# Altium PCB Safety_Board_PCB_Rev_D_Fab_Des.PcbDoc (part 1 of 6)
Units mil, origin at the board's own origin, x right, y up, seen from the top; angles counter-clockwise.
Board outline 11000 x 4400 mil, 6 copper layers (L1-TOP, L2-Plane, L3-Signal, L4-Signal, L5-Plane, L6-BOT); 712 components, 540 nets, 2214 pads, 875 vias.
Unrouted connection lines stored in the file: 3.
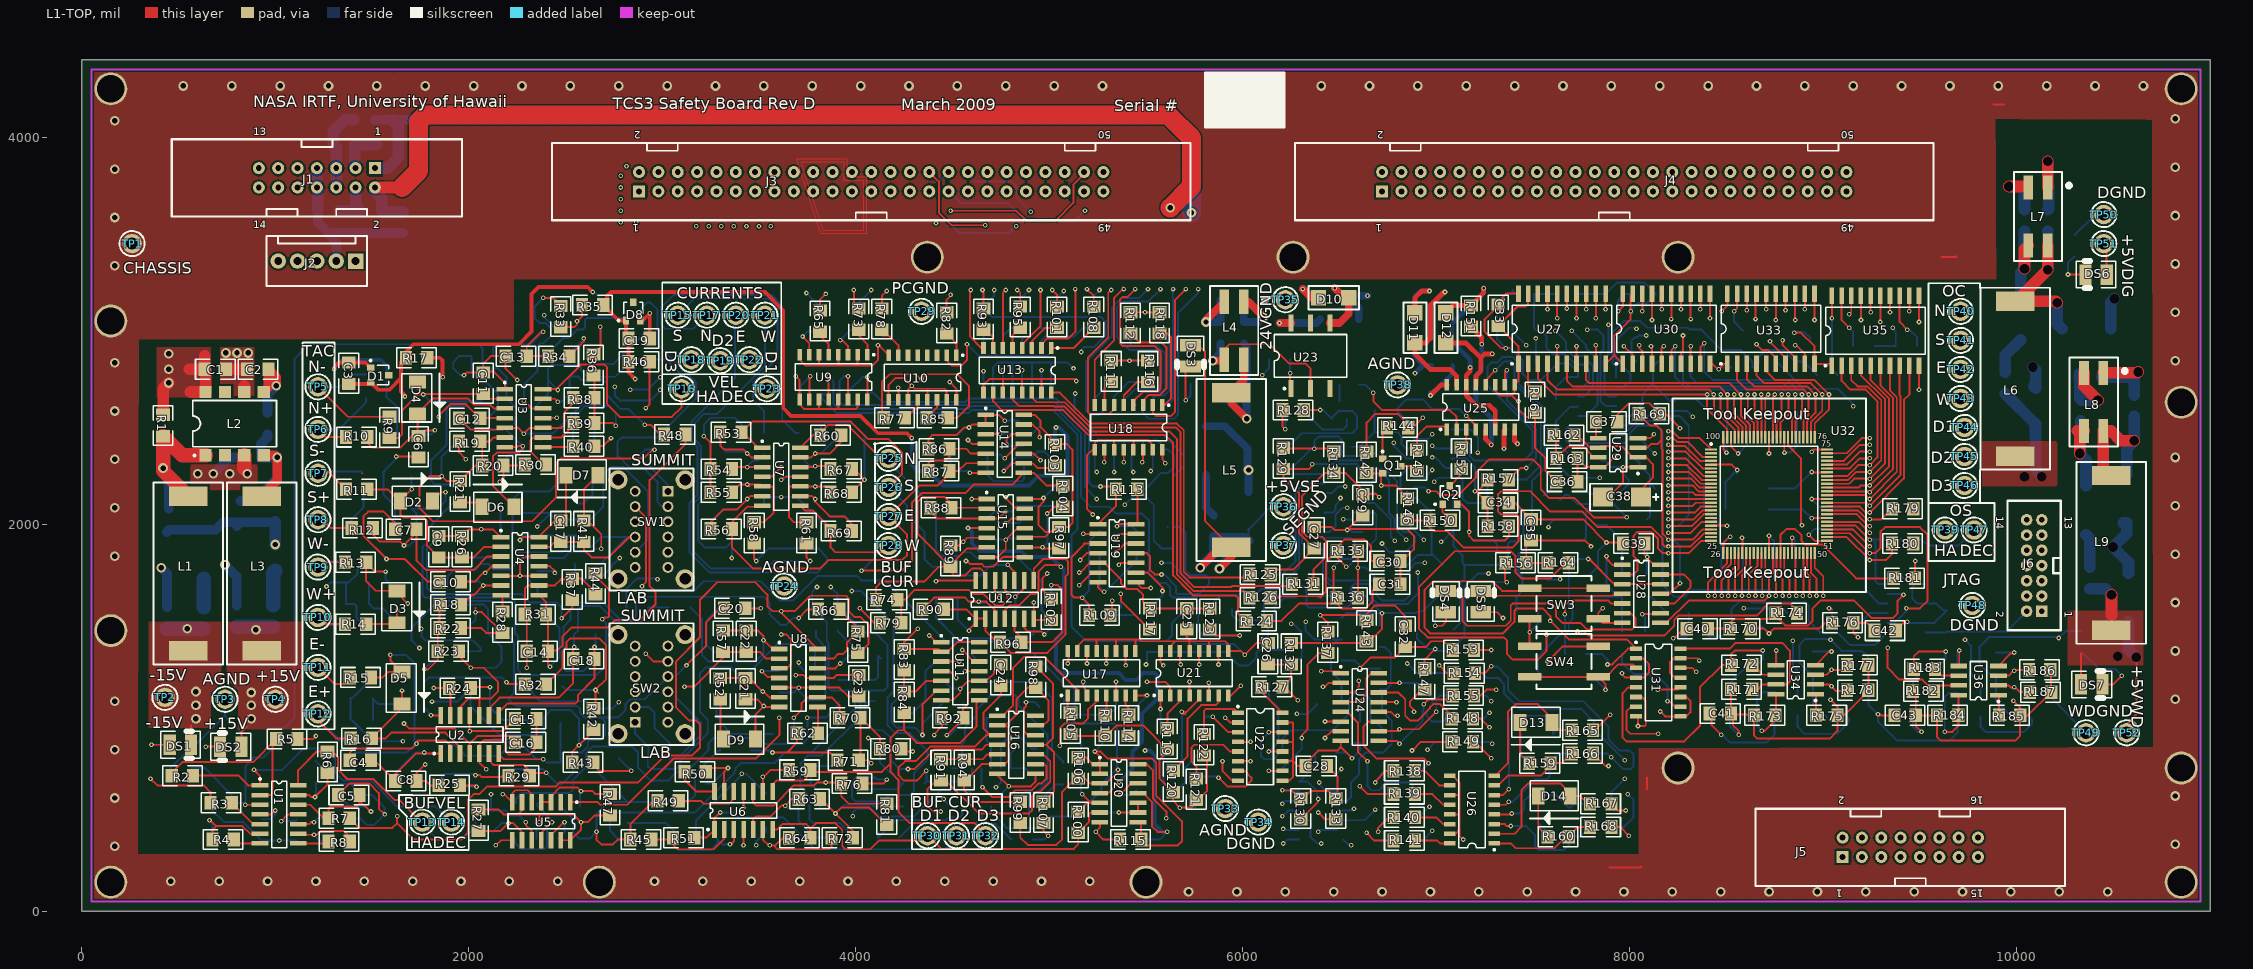
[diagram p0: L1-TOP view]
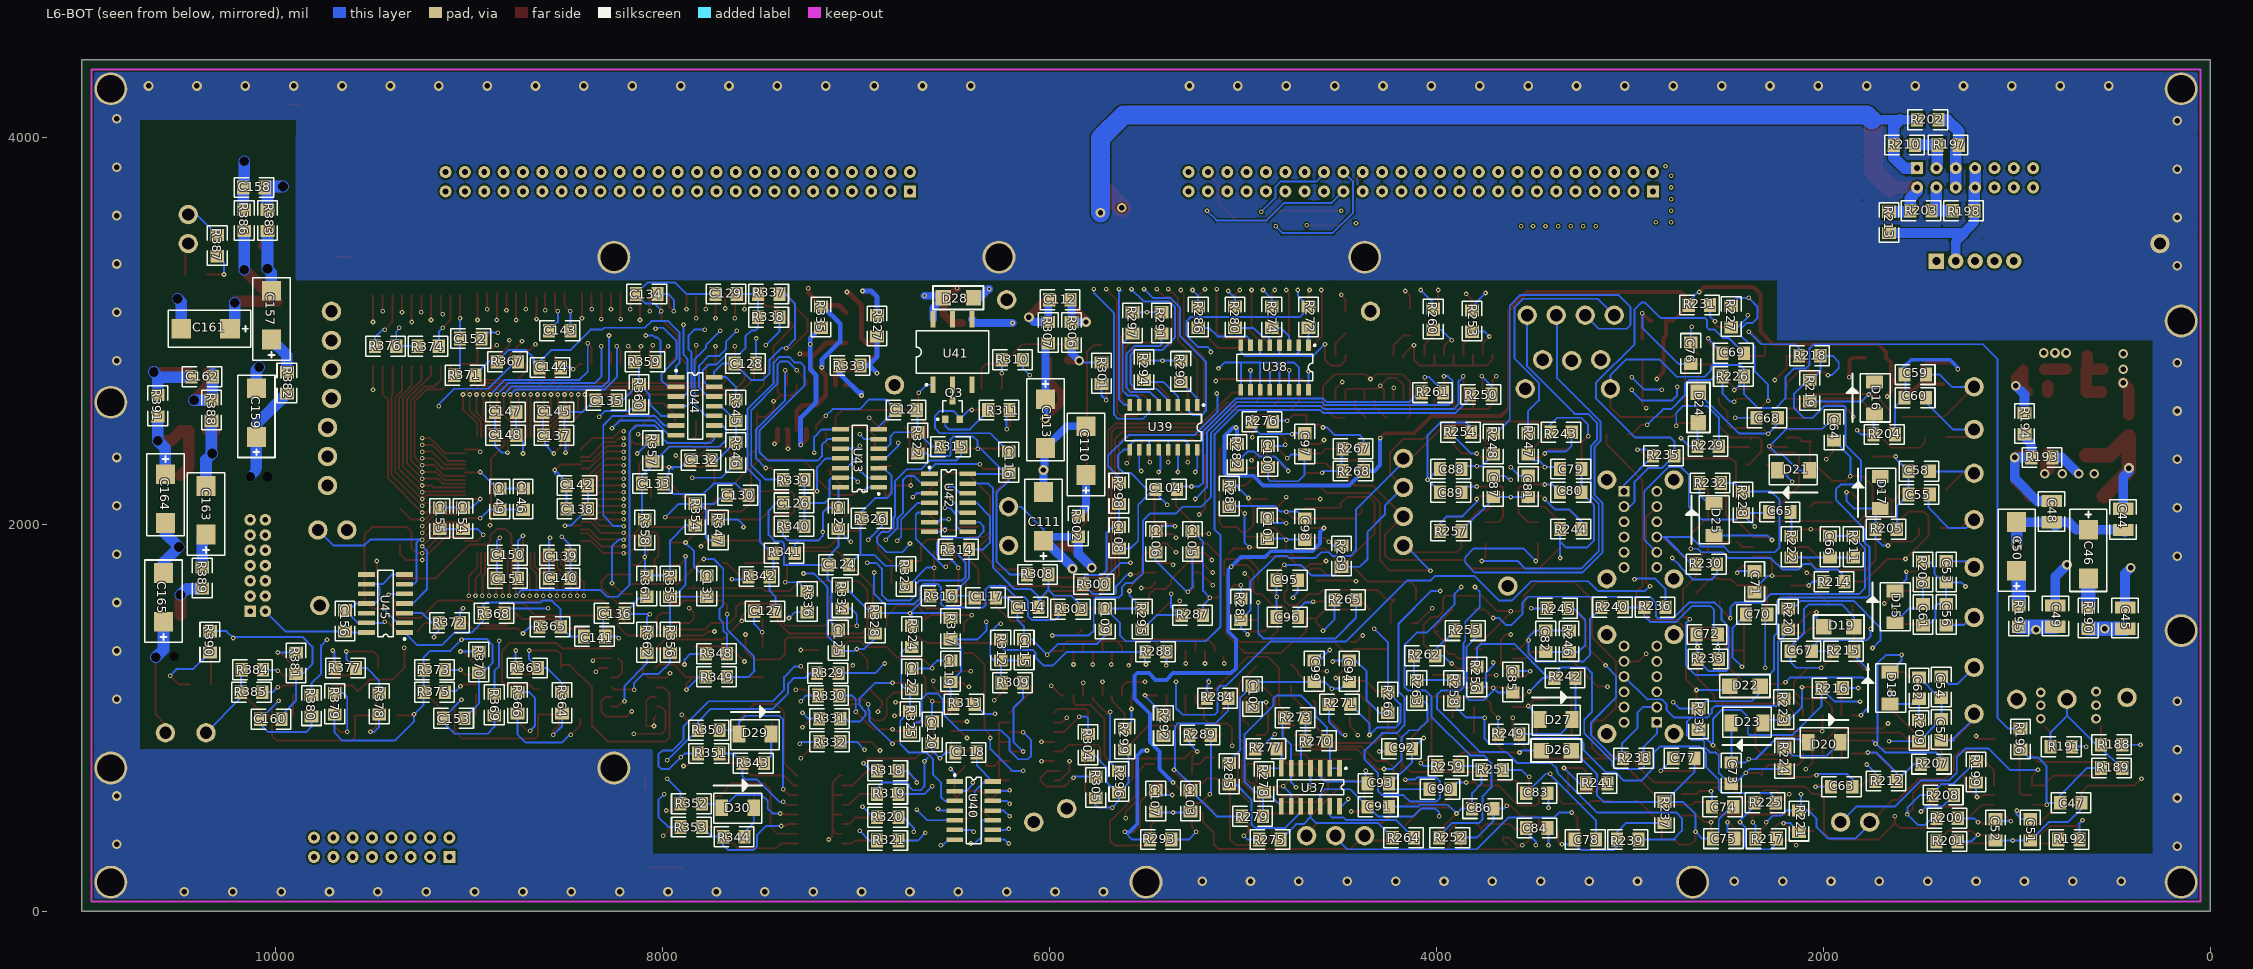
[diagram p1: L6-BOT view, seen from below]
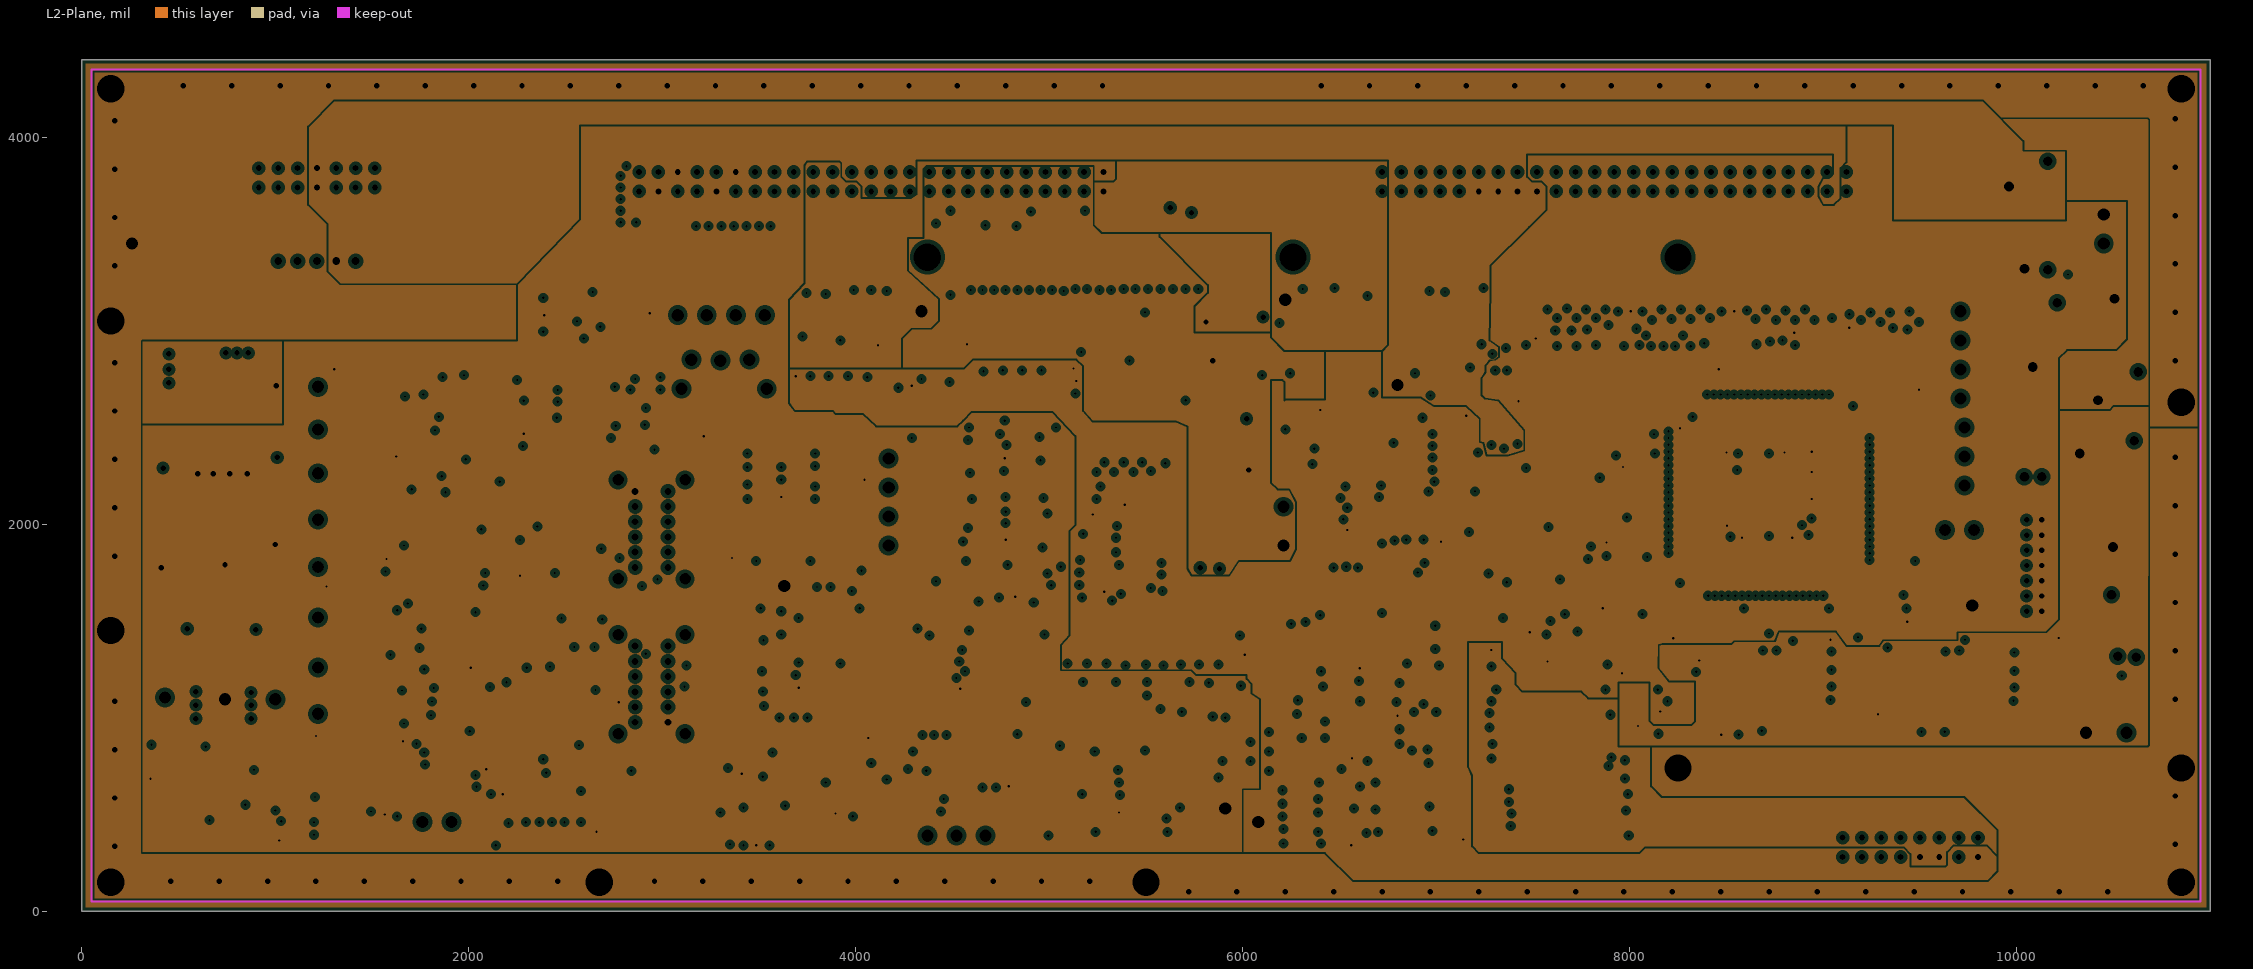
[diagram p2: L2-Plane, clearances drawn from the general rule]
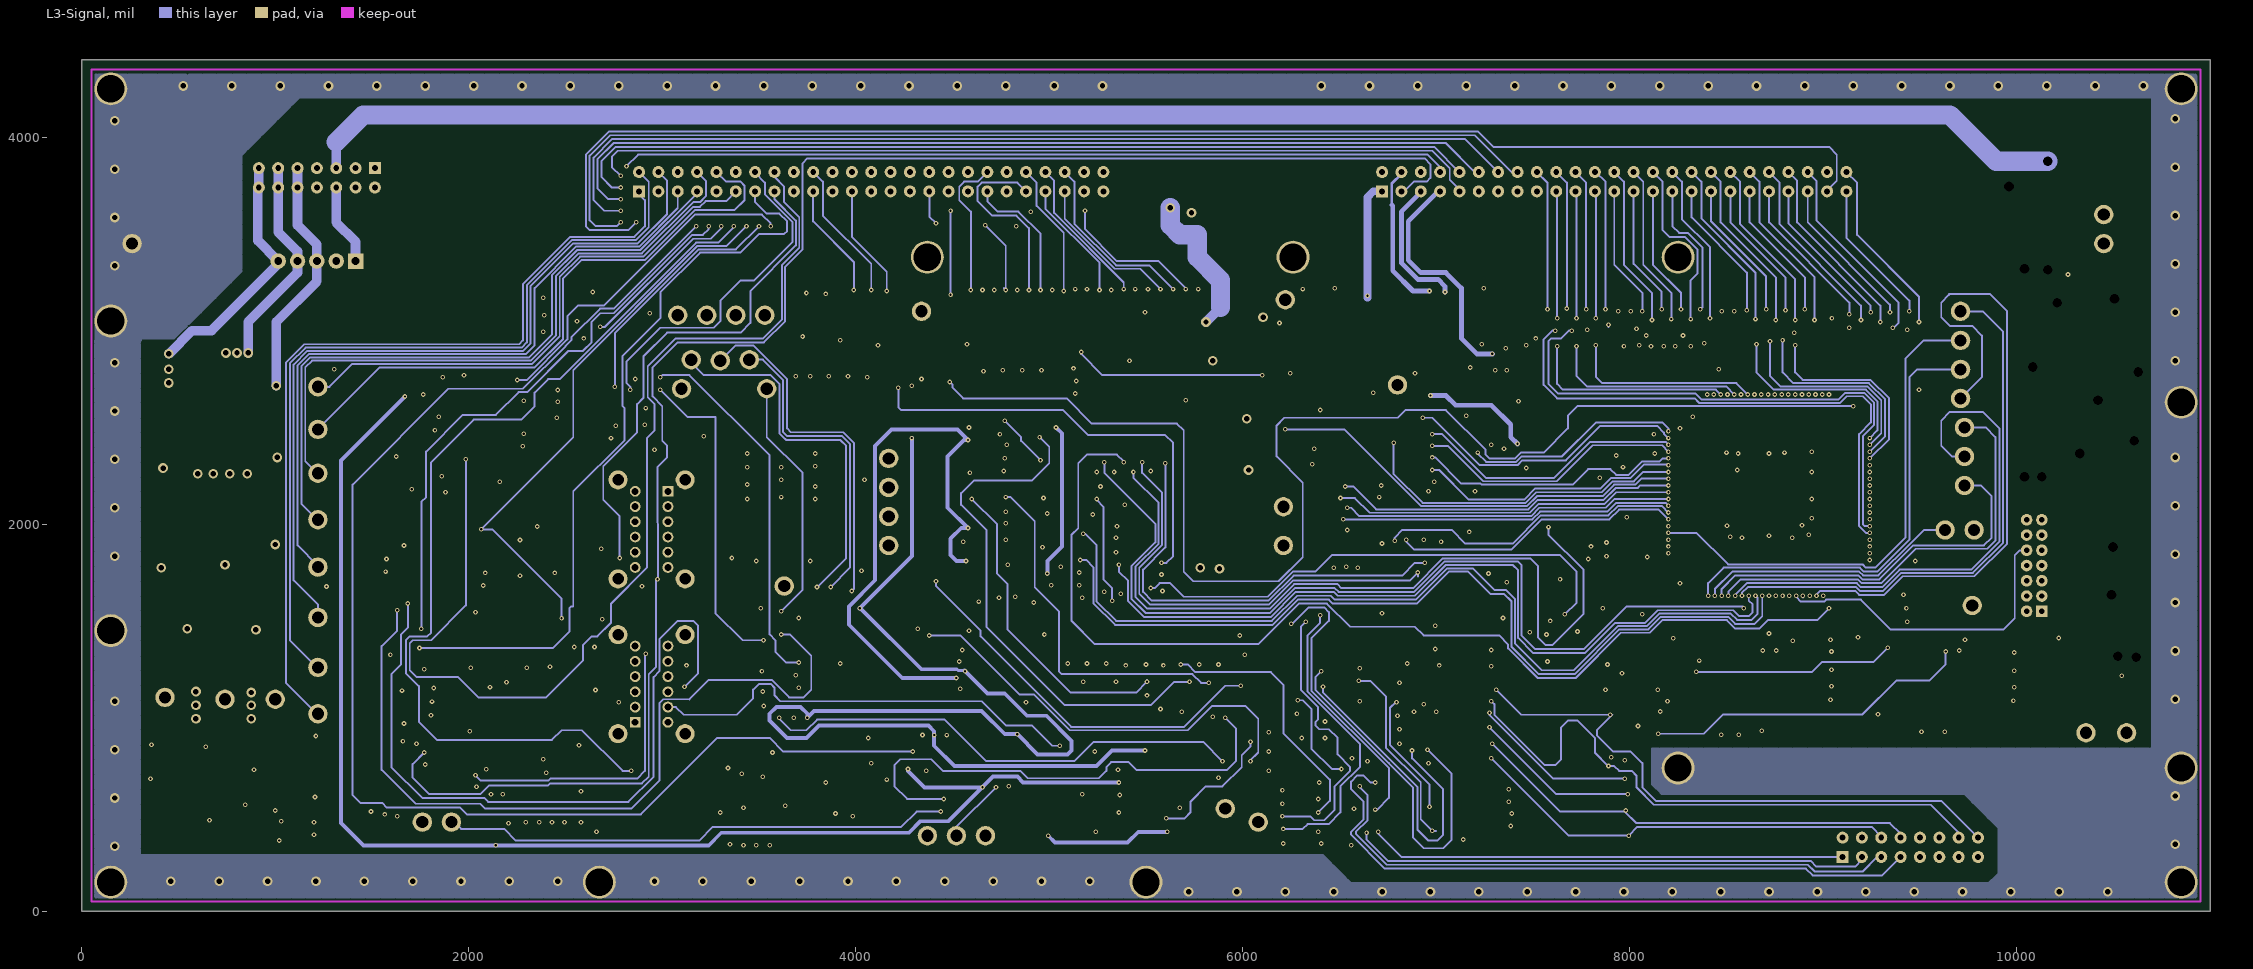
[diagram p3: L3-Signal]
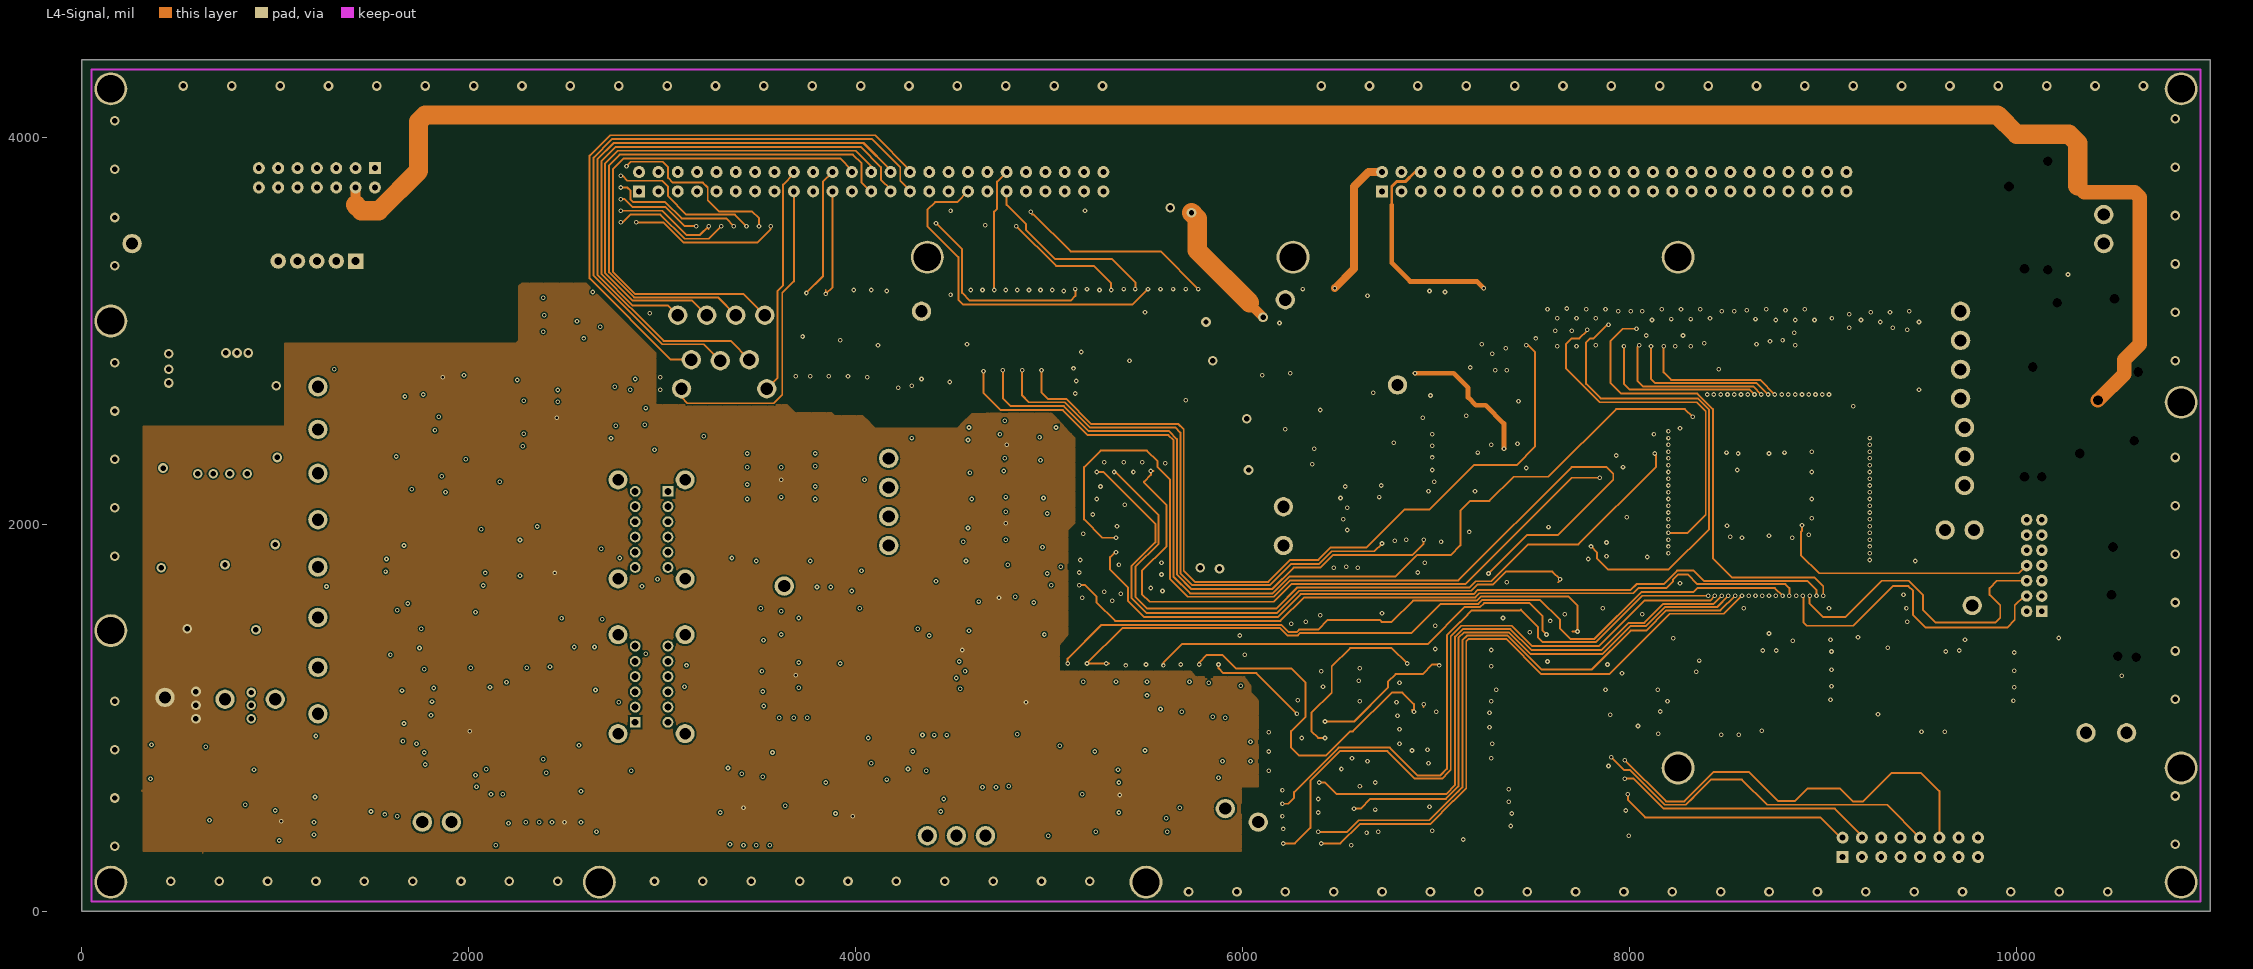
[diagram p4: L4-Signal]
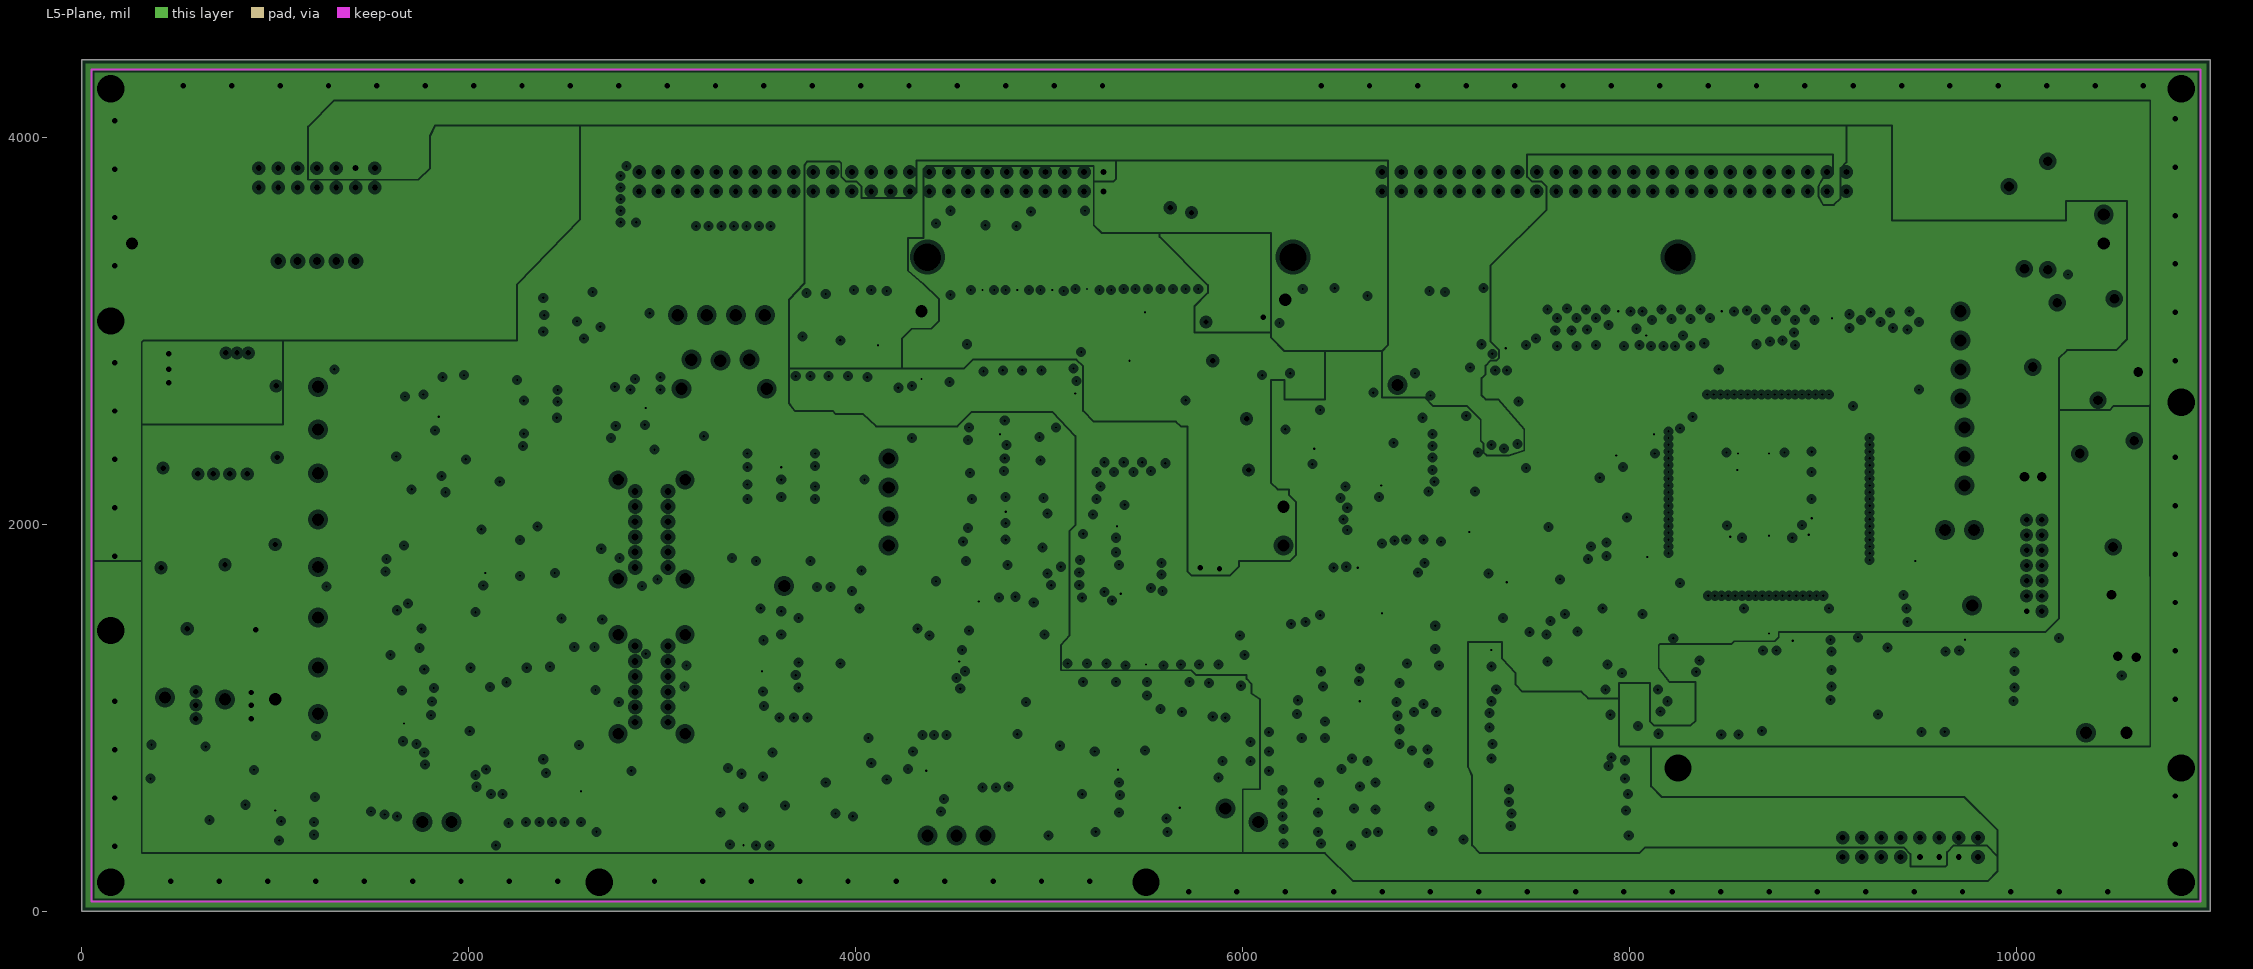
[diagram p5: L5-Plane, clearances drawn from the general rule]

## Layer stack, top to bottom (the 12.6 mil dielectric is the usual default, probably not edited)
L1-TOP: signal copper 1.4
Dielectric: core 12.6, FR-4, Dk 4.8
L2-Plane: plane copper 1.4, net (Multiple Nets)
Dielectric: prepreg 12.6, FR-4, Dk 4.8
L3-Signal: signal copper 1.4
Dielectric: core 12.6, FR-4, Dk 4.8
L4-Signal: signal copper 1.4
Dielectric: prepreg 12.6, FR-4, Dk 4.8
L5-Plane: plane copper 1.4, net (Multiple Nets)
Dielectric: core 12.6, FR-4, Dk 4.8
L6-BOT: signal copper 1.4

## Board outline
0,0 11000,0 11000,4400 0,4400 0,0

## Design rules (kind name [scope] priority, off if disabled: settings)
Clearance Clearance_1 [InPolygon vs IsPad] p1: gap=10
Clearance [All] p2: gap=7
ComponentClearance ComponentClearance_1 [All] p1: gap=2 collisioncheckmode=1
FanoutControl Fanout_BGA_1 [IsBGA] p1: bgadir=Out bgaviamode=Centered fanoutstyle=Auto fanoutdirection=Alternating viagrid=1 // Fanout_BGA (Default Rule)
FanoutControl Fanout_LCC_1 [IsLCC] p2: bgadir=Out bgaviamode=Centered fanoutstyle=Auto fanoutdirection=Alternating viagrid=1 // Fanout_LCC (Default Rule)
FanoutControl Fanout_SOIC_1 [IsSOIC] p3: bgadir=Out bgaviamode=Centered fanoutstyle=Auto fanoutdirection=Alternating viagrid=1 // Fanout_SOIC (Default Rule)
FanoutControl Fanout_Small_1 [(CompPinCount < 5)] p4: bgadir=Out bgaviamode=Centered fanoutstyle=Auto fanoutdirection=OutThenIn viagrid=1 // Fanout_Small (Default Rule)
FanoutControl Fanout_Default_1 [All] p5: bgadir=Out bgaviamode=Centered fanoutstyle=Auto fanoutdirection=Alternating viagrid=1 // Fanout_Default (Default Rule)
Height Height_1 [All] p1: minheight=0 maxheight=1000 prefheight=500
HoleSize HoleSize_1 [All] p1: absolutevalues=TRUE maxlimit=200 minlimit=1 maxpercent=80.000 minpercent=20.000
LayerPairs LayerPairs_1 [All] p1: enforce=TRUE
MatchedLengths "Encoder HA" [InNetClass('Encoder HA Nets')] p1: tolerance=100 amplitude=200 gap=20 style=90-Degree
MatchedLengths "Encoder DEC" [InNetClass('Encoder DEC Nets')] p2: tolerance=100 amplitude=200 gap=20 style=90-Degree
MatchedLengths JTAG [InNetClass('JTAG Nets')] p3: tolerance=50 amplitude=200 gap=20 style=90-Degree
PasteMaskExpansion PasteMaskExpansion_1 [All] p1: expansion=0
PlaneClearance PlaneClearance_1 [All] p1: clearance=20
PlaneConnect [All] p1: planeconnectstyle=Relief reliefexpansion=20 reliefentries=4 reliefconductorwidth=10 reliefairgap=10
PolygonConnect PolygonConnect_1 [All] p1: connectstyle=Direct reliefconductorwidth=10 reliefentries=4 polygonreliefangle="90 Angle"
RoutingLayers [All] p1: top layer=Horizontal mid layer 3="Not Used" mid layer 4="Not Used" bottom layer=Vertical
RoutingPriority RoutingPriority_1 [All] p1: routingpriority=0
RoutingTopology RoutingTopology_1 [All] p1: topology=Shortest
RoutingVias [All] p1: holewidth=28 width=50 viastyle="Through Hole" minholewidth=28 minwidth=50 maxholewidth=28 maxwidth=50
ShortCircuit ShortCircuit_1 [All] p1: allowed=FALSE
SolderMaskExpansion SolderMaskExpansion_1 [All] p1: expansion=4
TestPointUsage TestPointUsage_1 [All] p1: valid=0 allowmultiple=FALSE
Testpoint Testpoint_1 [All] p1: side=15 testpointundercomponent=TRUE minsize=40 maxsize=100 preferedsize=60 minholesize=0 maxholesize=40 preferedholesize=32 testpointgrid=1 style=1023 order=-539222988
UnRoutedNet UnRoutedNet_1 [All] p1:
Width [All] p1: maxlimit=250 minlimit=7 preferedwidth=10 toplayer_prefwidth=20 minimp=50.000000 maximp=50.000000 favimp=50.000000
1 further rules are at their usual default settings.

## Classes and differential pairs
component class Sheet_Symbol_WD: C39 C41 C43 C131 C136 C153 C160 DS4 DS5 R171 R172 R173 R175 R177 R178 R182 R183 R184 R185 R186 R187 R334 R336 R348 R349 R355 R356 R361 R362 R363 R364 R366 R369 R370 R373 R375 R377 R378 R379 R380 R381 R384 R385 SW3 SW4 U28 U31 U34 U36
component class Sheet_Symbol_Power_Filter: C1 C2 C3 C19 C44 C45 C46 C48 C49 C50 C110 C111 C112 C113 C157 C158 C159 C161 C162 C163 C164 C165 D1 D8 DS1 DS2 DS3 DS6 DS7 L1 L2 L3 L4 L5 L6 L7 L8 L9 R1 R17 R46 R188 R190 R191 R193 R194 R195 R197 R198 R202 R203 R210 R213 R301 R302 R306 R307 R382 R383 R386 R387 R388 R389 R390 R391 TP1 TP2 TP3 TP4 TP24 TP29 TP33 TP34 TP36 TP37 TP38 TP48 TP49 TP50 TP51 TP52
component class SB_PG1: J1 J2 J3 J4 J5
component class Sheet_Symbol_CPLD: C33 C36 C37 C38 C134 C137 C138 C139 C140 C142 C143 C145 C146 C147 C148 C149 C150 C151 C152 C154 C155 J6 R161 R162 R163 R169 R179 R180 R181 R374 R376 U27 U29 U30 U32 U33 U35
component class Sheet_Symbol_Dec_Tach: C6 C7 C9 C10 C11 C12 C13 C14 C17 C55 C58 C59 C60 C64 C65 C66 C67 C68 C69 C70 C71 C76 D2 D4 D6 D7 D16 D17 D19 D21 D24 D25 R9 R10 R11 R12 R18 R19 R20 R21 R22 R23 R26 R28 R30 R31 R33 R34 R35 R36 R37 R38 R39 R40 R41 R44 R48 R110 R204 R205 R211 R214 R215 R218 R219 R222 R226 R227 R228 R229 R230 R231 R232 R235 SW1 TP5 TP6 TP7 TP8 TP16 U3 U4
component class Sheet_Symbol_Encoder: C120 D13 D14 D29 D30 R138 R139 R140 R141 R148 R149 R153 R154 R155 R159 R160 R165 R166 R167 R168 R318 R319 R320 R321 R329 R330 R331 R332 R343 R344 R350 R351 R352 R353 U24 U26
component class Sheet_Symbol_HA_Tach: C4 C8 C15 C16 C18 C20 C21 C22 C23 C53 C54 C56 C57 C61 C62 C63 C72 C73 C77 C82 C85 C92 D3 D5 D9 D15 D18 D20 D22 D23 D26 D27 R13 R14 R15 R16 R24 R25 R29 R32 R42 R43 R52 R57 R62 R66 R70 R71 R75 R80 R206 R207 R209 R212 R216 R220 R223 R224 R233 R234 R236 R238 R240 R242 R245 R246 R249 R255 R256 R258 R259 R262 R263 R284 SW2 TP9 TP10 TP11 TP12 TP23 U2 U8
component class Sheet_Symbol_Input_Buffer: C25 C104 C105 C106 C108 C109 C121 C124 C128 C129 C135 C144 R65 R73 R78 R82 R109 R113 R117 R123 R250 R253 R260 R261 R272 R274 R280 R286 R287 R295 R298 R300 R315 R322 R323 R326 R337 R338 R359 R360 R367 R371 U9 U10 U19 U38 U44
component class Sheet_Symbol_Overcurrent: C35 C79 C81 C87 C88 C95 C96 C98 C101 C119 R53 R54 R60 R67 R74 R79 R88 R89 R90 R96 R102 R120 R156 R164 R243 R247 R248 R254 R265 R269 R281 R299 R313 R317 TP15 TP17 TP25 TP26 TP40 TP41 U7 U12 U15 U21
component class Sheet_Symbol_Overspeed: C5 C24 C32 C40 C47 C51 C52 C102 R2 R5 R6 R7 R27 R47 R91 R94 R98 R99 R100 R105 R137 R143 R170 R174 R189 R196 R199 R208 R217 R221 R225 R305 TP13 TP14 TP39 TP47 U1 U16 U17
component class Sheet_Symbol_Relays: C34 C126 D10 D11 D12 D28 Q1 Q2 Q3 R128 R142 R144 R145 R146 R150 R151 R152 R157 R158 R310 R311 R327 R333 R335 R339 R340 TP35 U23 U25 U41
component class Sheet_Symbol_Spares: C74 C75 R3 R4 R8 R49 R50 R77 R85 R114 R192 R200 R201 R241 R264 R275 R285 R288 R292 U5

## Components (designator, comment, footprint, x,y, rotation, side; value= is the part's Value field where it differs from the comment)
C1 "1uF" 1206 690,2800 r0 top locked (schematic designator C2)
C2 "1uF" 1206 910,2800 r0 top locked (schematic designator C1)
C3 "1uF" 1206 1380,2780 r270 top locked (schematic designator C4)
C4 "0.022uF" 1206 1440,780 r180 top locked (schematic designator C63)
C5 "1uF" 1206 1380,600 r0 top locked (schematic designator C142)
C6 "0.022uF" 1206 1740,2400 r90 top locked (schematic designator C38)
C7 "0.022uF" 1206 1674.65,1973.11 r0 top locked (schematic designator C40)
C8 "0.068uF" 1206 1674.65,673.11 r0 top locked (schematic designator C68)
C9 "0.022uF" 1206 1844.65,1883.11 r270 top locked (schematic designator C39)
C10 "0.1uF" 1206 1904.65,1703.11 r0 top locked (schematic designator C33)
C11 "0.022uF" 1206 2074.65,2728.11 r270 top locked (schematic designator C37)
C12 "0.1uF" 1206 2004.65,2548.11 r0 top locked (schematic designator C26)
C13 "0.068uF" 1206 2244.65,2868.11 r0 top locked (schematic designator C43)
C14 "0.22uF" 1206 2354.65,1343.11 r0 top locked (schematic designator C47)
C15 "0.1uF" 1206 2294.65,993.11 r180 top locked (schematic designator C60)
C16 "0.1uF" 1206 2294.65,873.11 r180 top locked (schematic designator C57)
C17 "2200pF" 1206 2474.65,1963.11 r90 top locked (schematic designator C42)
C18 "1uF" 1206 2594.65,1303.11 r0 top locked (schematic designator C48)
C19 "1uF" 1206 2880,2960 r180 top locked (schematic designator C6)
C20 "0.33uF" 1206 3373.43,1565 r180 top locked (schematic designator C69)
C21 "2200pF" 1206 3430,1150 r270 top locked (schematic designator C65)
C22 "0.022uF" 1206 3433.43,1395 r270 top locked (schematic designator C61)
C23 "0.1uF" 1206 4015,1165 r90 top locked (schematic designator C53)
C24 "0.1uF" 1206 4750,1220 r270 top locked (schematic designator C151)
C25 "1uF" 1206 5710,1510 r90 top locked (schematic designator C112)
C26 "1uF" 1206 6130,1330 r270 top locked (schematic designator C171)
C27 "1uF" 1206 6370,1930 r270 top locked (schematic designator C107)
C28 "1uF" 1206 6380,750 r0 top locked (schematic designator C157)
C29 "1uF" 1206 6620,2100 r90 top locked (schematic designator C94)
C30 "1uF" 1206 6760,1810 r180 top locked (schematic designator C109)
C31 "1uF" 1206 6760,1690 r180 top locked (schematic designator C96)
C32 "1uF" 1206 6840,1420 r90 top locked (schematic designator C143)
C33 "0.1uF" 1206 7320,3080 r90 top locked (schematic designator C30)
C34 "1uF" 1206 7320,2110 r180 top locked (schematic designator C91)
C35 "1uF" 1206 7490,1970 r270 top locked (schematic designator C100)
C36 "0.1uF" 1206 7675,2220 r0 top locked (schematic designator C77)
C37 "0.01uF" 1206 7880,2530 r180 top locked (schematic designator C83)
C38 "10uF_25V" CAP_EIA_6032 7960,2140 r180 top locked (schematic designator C84)
C39 "0.1uF" 1206 8020,1900 r0 top locked (schematic designator C134)
C40 "1uF" 1206 8350,1460 r0 top locked (schematic designator C122)
C41 "0.1uF" 1206 8467.97,1021.92 r0 top (schematic designator C87)
C42 "1uF" 1206 9320,1450 r180 top locked (schematic designator C120)
C43 "0.1uF" 1206 9422.96,1011.92 r0 top locked (schematic designator C89)
C44 "22uF_15V" 1210 450,2025 r90 bottom locked (schematic designator C10)
C45 "22uF_15V" 1210 440,1515 r270 bottom locked (schematic designator C11)
C46 "100uF_25V" CAP_EIA_7343 630,1845 r270 bottom locked (schematic designator C13)
C47 "1uF" 1206 720,560 r0 bottom locked (schematic designator C144)
C48 "22uF_15V" 1210 820,2065 r90 bottom locked (schematic designator C9)
C49 "22uF_15V" 1210 800,1525 r270 bottom locked (schematic designator C8)
C50 "100uF_25V" CAP_EIA_7343 1000,1885 r90 bottom locked (schematic designator C12)
C51 "0.1uF" 1206 930,420 r90 bottom locked (schematic designator C152)
C52 "0.1uF" 1206 1110,420 r90 bottom locked (schematic designator C155)
C53 "0.1uF" 1206 1364.65,1753.11 r90 bottom locked (schematic designator C51)
C54 "0.1uF" 1206 1389.65,1158.11 r90 bottom locked (schematic designator C58)
C55 "0.1uF" 1206 1504.65,2153.11 r180 bottom locked (schematic designator C35)
C56 "0.1uF" 1206 1364.65,1533.11 r270 bottom locked (schematic designator C52)
C57 "0.1uF" 1206 1389.65,938.11 r270 bottom locked (schematic designator C59)
C58 "0.1uF" 1206 1504.65,2273.11 r180 bottom locked (schematic designator C34)
C59 "0.1uF" 1206 1524.65,2773.11 r180 bottom locked (schematic designator C27)
C60 "0.1uF" 1206 1524.65,2653.11 r180 bottom locked (schematic designator C28)
C61 "0.022uF" 1206 1484.65,1533.11 r90 bottom locked (schematic designator C62)
C62 "0.022uF" 1206 1504.65,1153.11 r270 bottom locked (schematic designator C64)
C63 "0.33uF" 1206 1904.65,643.11 r180 bottom locked (schematic designator C70)
C64 "2200pF" 1206 1944.65,2488.11 r90 bottom locked (schematic designator C41)
C65 "0.33uF" 1206 2224.65,2063.11 r0 bottom locked (schematic designator C46)
C66 "0.068uF" 1206 1964.65,1883.11 r270 bottom locked (schematic designator C44)
C67 "0.1uF" 1206 2114.65,1343.11 r180 bottom locked (schematic designator C32)
C68 "0.1uF" 1206 2290,2550 r0 bottom locked (schematic designator C29)
C69 "0.33uF" 1206 2464.65,2883.11 r180 bottom locked (schematic designator C45)
C70 "1uF" 1206 2344.65,1533.11 r0 bottom locked (schematic designator C24)
C71 "0.1uF" 1206 2354.65,1703.11 r90 bottom locked (schematic designator C36)
C72 "0.22uF" 1206 2600,1430 r0 bottom locked (schematic designator C71)
C73 "2200pF" 1206 2474.65,713.11 r90 bottom locked (schematic designator C66)
C74 "0.1uF" 1206 2520,540 r0 bottom locked (schematic designator C131)
C75 "0.1uF" 1206 2515,375 r180 bottom locked (schematic designator C133)
C76 "0.1uF" 1206 2684.65,2883.11 r90 bottom locked (schematic designator C25)
C77 "0.1uF" 1206 2720,790 r0 bottom locked (schematic designator C56)
C78 "1uF" 1206 3230,370 r0 bottom locked (schematic designator C170)
C79 "1uF" 1206 3305,2285 r0 bottom locked (schematic designator C121)
C80 "1uF" 1206 3305,2165 r0 bottom locked (schematic designator C156)
C81 "0.1uF" 1206 3525,2195 r90 bottom locked (schematic designator C180)
C82 "0.068uF" 1206 3433.43,1395 r270 bottom locked (schematic designator C67)
C83 "0.1uF" 1206 3480,610 r180 bottom locked (schematic designator C127)
C84 "0.1uF" 1206 3480,430 r180 bottom locked (schematic designator C124)
C85 "0.1uF" 1206 3605,1185 r90 bottom locked (schematic designator C50)
C86 "1uF" 1206 3760,530 r180 bottom locked (schematic designator C128)
C87 "0.1uF" 1206 3705,2195 r90 bottom locked (schematic designator C183)
C88 "1uF" 1206 3925,2285 r180 bottom locked (schematic designator C118)
C89 "1uF" 1206 3925,2165 r180 bottom locked (schematic designator C158)
C90 "1uF" 1206 3980,630 r180 bottom locked (schematic designator C172)
C91 "0.1uF" 1206 4300,540 r0 bottom locked (schematic designator C177)
C92 "0.1uF" 1206 4180,840 r0 bottom locked (schematic designator C49)
C93 "0.1uF" 1206 4300,660 r0 bottom locked (schematic designator C174)
C94 "0.1uF" 1206 4450,1240.12 r90 bottom locked (schematic designator C179)
C95 "0.1uF" 1206 4770,1710 r180 bottom locked (schematic designator C125)
C96 "0.1uF" 1206 4770,1520 r180 bottom locked (schematic designator C123)
C97 "0.1uF" 1206 4680,2415 r90 bottom locked (schematic designator C160)
C98 "0.1uF" 1206 4680,1975 r90 bottom locked (schematic designator C126)
C99 "0.1uF" 1206 4630,1240.12 r90 bottom locked (schematic designator C182)
C100 "0.1uF" 1206 4870,2350 r90 bottom locked (schematic designator C163)
C101 "0.1uF" 1206 4873.43,1980 r90 bottom locked (schematic designator C130)
C102 "0.1uF" 1206 4950,1110 r270 bottom locked (schematic designator C154)
C103 "0.1uF" 1206 5270,570 r90 bottom locked (schematic designator C132)
C104 "1uF" 1206 5395.12,2180 r180 bottom locked (schematic designator C108)
C105 "1uF" 1206 5260,1910 r90 bottom locked (schematic designator C110)
C106 "0.1uF" 1206 5450,1910 r90 bottom locked (schematic designator C119)
C107 "0.1uF" 1206 5450,570 r90 bottom locked (schematic designator C135)
C108 "1uF" 1206 5640,1930 r90 bottom locked (schematic designator C116)
C109 "1uF" 1206 5710,1510 r90 bottom locked (schematic designator C114)
C110 "470uF_10V" CAP_EIA_7343 5810,2380 r90 bottom locked (schematic designator C22)
C111 "100uF_25V" CAP_EIA_7343 6030,2040 r90 bottom locked (schematic designator C19)
C112 "1uF" 1206 5945,3160 r0 bottom locked (schematic designator C7)
C113 "100uF_25V" CAP_EIA_7343 6020,2520 r270 bottom locked (schematic designator C18)
C114 "1uF" 1206 6110,1570 r180 bottom locked (schematic designator C98)
C115 "1uF" 1206 6130,1350 r270 bottom locked (schematic designator C173)
C116 "0.1uF" 1206 6210,2320 r270 bottom locked (schematic designator C105)
C117 "1uF" 1206 6330,1620 r0 bottom locked (schematic designator C111)
C118 "0.1uF" 1206 6430,820 r180 bottom locked (schematic designator C117)
C119 "1uF" 1206 6510,1240 r270 bottom locked (schematic designator C145)
C120 "0.1uF" 1206 6605,925 r90 bottom locked (schematic designator C23)
C121 "1uF" 1206 6740,2590 r180 bottom locked (schematic designator C97)
C122 "1uF" 1206 6710,1200 r270 bottom locked (schematic designator C129)
C123 "0.1uF" 1206 7090,2030 r90 bottom locked (schematic designator C106)
C124 "1uF" 1206 7090,1790 r180 bottom locked (schematic designator C95)
C125 "1uF" 1206 7090,1400 r270 bottom locked (schematic designator C101)
C126 "1uF" 1206 7320,2110 r180 bottom locked (schematic designator C92)
C127 "1uF" 1206 7470,1550 r180 bottom locked (schematic designator C99)
C128 "0.1uF" 1206 7570,2830 r0 bottom locked (schematic designator C140)
C129 "1uF" 1206 7670,3190 r180 bottom locked (schematic designator C104)
C130 "1uF" 1206 7610,2150 r0 bottom locked (schematic designator C93)
C131 "1uF" 1206 7770,1680 r270 bottom locked (schematic designator C85)
C132 "1uF" 1206 7800,2330 r180 bottom locked (schematic designator C103)
C133 "1uF" 1206 8050,2210 r0 bottom locked (schematic designator C102)
C134 "0.1uF" 1206 8080,3190 r180 bottom locked (schematic designator C31)
C135 "1uF" 1206 8290,2640 r180 bottom locked (schematic designator C115)
C136 "1uF" 1206 8250,1540 r180 bottom locked (schematic designator C86)
C137 "0.1uF" 1206 8560,2460 r0 bottom locked (schematic designator C139)
C138 "1uF" 1206 8440,2080 r0 bottom locked (schematic designator C136)
C139 "1uF" 1206 8530,1840 r180 bottom locked (schematic designator C76)
C140 "0.1uF" 1206 8530,1720 r180 bottom locked (schematic designator C82)
C141 "1uF" 1206 8350,1420 r0 bottom locked (schematic designator C159)
C142 "0.1uF" 1206 8440,2200 r0 bottom locked (schematic designator C138)
C143 "0.1uF" 1206 8530,3000 r180 bottom locked (schematic designator C54)
C144 "1uF" 1206 8580,2810 r0 bottom locked (schematic designator C113)
C145 "1uF" 1206 8560,2580 r0 bottom locked (schematic designator C137)
C146 "0.1uF" 1206 8720,2130 r270 bottom locked (schematic designator C78)
C147 "0.1uF" 1206 8810,2580 r180 bottom locked (schematic designator C79)
C148 "1uF" 1206 8810,2460 r180 bottom locked (schematic designator C73)
C149 "1uF" 1206 8840,2130 r270 bottom locked (schematic designator C72)
C150 "1uF" 1206 8800,1840 r180 bottom locked (schematic designator C75)
C151 "0.1uF" 1206 8800,1720 r180 bottom locked (schematic designator C81)
C152 "0.1uF" 1206 8990,2960 r0 bottom locked (schematic designator C55)
C153 "0.1uF" 1206 9077.96,996.92 r0 bottom locked (schematic designator C88)
C154 "1uF" 1206 9030,2030 r270 bottom locked (schematic designator C74)
C155 "0.1uF" 1206 9150,2030 r270 bottom locked (schematic designator C80)
C156 "0.1uF" 1206 9640,1500 r270 bottom locked (schematic designator C167)
C157 "470uF_10V" CAP_EIA_7343 10020,3080 r90 bottom locked (schematic designator C21)
C158 "1uF" 1206 10110,3740 r0 bottom locked (schematic designator C5)
C159 "100uF_25V" CAP_EIA_7343 10097.96,2576.92 r90 bottom locked (schematic designator C17)
C160 "0.1uF" 1206 10022.96,991.92 r0 bottom locked (schematic designator C90)
C161 "100uF_25V" CAP_EIA_7343 10360,3010 r0 bottom locked (schematic designator C16)
C162 "1uF" 1206 10377.96,2761.92 r0 bottom locked (schematic designator C3)
C163 "470uF_10V" CAP_EIA_7343 10357.96,2071.92 r90 bottom locked (schematic designator C20)
C164 "100uF_25V" CAP_EIA_7343 10567.96,2131.92 r270 bottom locked (schematic designator C14)
C165 "100uF_25V" CAP_EIA_7343 10577.96,1621.92 r90 bottom locked (schematic designator C15)
D1 "LM4040DIM3-5.0/NOPB" SOT23 1540,2770 r270 top locked (schematic designator D29)
D2 "RS1DB-13" "DO-214AA (SMB) & MARKING" 1730,2120 r0 top locked (schematic designator D10)
D3 "RS1DB-13" "DO-214AA (SMB) & MARKING" 1629.65,1573.11 r270 top locked (schematic designator D16)
D4 "RS1DB-13" "DO-214AA (SMB) & MARKING" 1734.65,2653.11 r270 top locked (schematic designator D6)
D5 "RS1DB-13" "DO-214AA (SMB) & MARKING" 1654.65,1153.11 r270 top locked (schematic designator D20)
D6 "RS1DB-13" "DO-214AA (SMB) & MARKING" 2150,2090 r0 top locked (schematic designator D8)
D7 "RS1DB-13" "DO-214AA (SMB) & MARKING" 2584.65,2253.11 r180 top locked (schematic designator D9)
D8 "LM4040DIM3-5.0/NOPB" SOT23 2850,3100 r0 top locked (schematic designator D30)
D9 "RS1DB-13" "DO-214AA (SMB) & MARKING" 3400,890 r0 top locked (schematic designator D18)
D10 "SMAJ26CA" "DO-214AC (SMA)" 6470,3170 r180 top locked (schematic designator D27)
D11 "SMAJ26CA" "DO-214AC (SMA)" 6890,3015 r90 top locked (schematic designator D25)
D12 "SMAJ26CA" "DO-214AC (SMA)" 7050,3015 r90 top locked (schematic designator D28)
D13 "RS1DB-13" "DO-214AA (SMB) & MARKING" 7515,975 r180 top locked (schematic designator D4)
D14 "RS1DB-13" "DO-214AA (SMB) & MARKING" 7610,595 r180 top locked (schematic designator D1)
D15 "RS1DB-13" "DO-214AA (SMB) & MARKING" 1629.65,1573.11 r90 bottom locked (schematic designator D17)
D16 "RS1DB-13" "DO-214AA (SMB) & MARKING" 1734.65,2653.11 r90 bottom locked (schematic designator D7)
D17 "RS1DB-13" "DO-214AA (SMB) & MARKING" 1704.65,2163.11 r90 bottom locked (schematic designator D11)
D18 "RS1DB-13" "DO-214AA (SMB) & MARKING" 1654.65,1153.11 r90 bottom locked (schematic designator D21)
D19 "1SMA10CAT3G" "DO-214AC (SMA)" 1920,1470 r0 bottom locked (schematic designator D14)
D20 "RS1DB-13" "DO-214AA (SMB) & MARKING" 1994.65,873.11 r180 bottom locked (schematic designator D22)
D21 "RS1DB-13" "DO-214AA (SMB) & MARKING" 2154.65,2278.11 r0 bottom locked (schematic designator D5)
D22 "1SMA10CAT3G" "DO-214AC (SMA)" 2404.65,1163.11 r0 bottom locked (schematic designator D24)
D23 "RS1DB-13" "DO-214AA (SMB) & MARKING" 2394.65,973.11 r0 bottom locked (schematic designator D19)
D24 "1SMA10CAT3G" "DO-214AC (SMA)" 2644.65,2603.11 r270 bottom locked (schematic designator D13)
D25 "RS1DB-13" "DO-214AA (SMB) & MARKING" 2564.65,2023.11 r90 bottom locked (schematic designator D12)
D26 "1SMA10CAT3G" "DO-214AC (SMA)" 3380,830 r0 bottom locked (schematic designator D23)
D27 "RS1DB-13" "DO-214AA (SMB) & MARKING" 3380,990 r180 bottom locked (schematic designator D15)
D28 "SMAJ26CA" "DO-214AC (SMA)" 6470,3170 r0 bottom locked (schematic designator D26)
D29 "RS1DB-13" "DO-214AA (SMB) & MARKING" 7520,915 r180 bottom locked (schematic designator D3)
D30 "RS1DB-13" "DO-214AA (SMB) & MARKING" 7610,535 r180 bottom locked (schematic designator D2)
DS1 "LTST-C930KGKT" LED_1210 510,860 r0 top locked (schematic designator DS4)
DS2 "LTST-C930KGKT" LED_1210 770,850 r180 top locked (schematic designator DS3)
DS3 "LTST-C930KGKT" LED_1210 5730,2870 r270 top locked (schematic designator DS7)
DS4 "LTST-C930KGKT" LED_1210 7050,1600 r90 top locked (schematic designator DS2)
DS5 "LTST-C930KGKT" LED_1210 7230,1600 r90 top locked (schematic designator DS1)
DS6 "LTST-C930KGKT" LED_1210 10410,3290 r180 top locked
DS7 "LTST-C930KGKT" LED_1210 10387.97,1171.92 r0 top locked (schematic designator DS5)
J1 "Header_14_(7X2)_STR_SHD_LATCH_col1" 5499922-2 1515,3840 r270 top locked (schematic designator J3)
J2 "*" 22-23-2051 1215,3360 r90 top locked (schematic designator J5)
J3 "Header_50_(25X2)_STR_SHD_LATCH_col1" 1-5499923-0 2880,3720 r90 top locked (schematic designator J1)
J4 "Header_50_(25X2)_STR_SHD_LATCH_col1" 1-5499923-0 6720,3720 r90 top locked (schematic designator J2)
J5 "Header_16_(8X2)_STR_SHD_LATCH_col1" 5499922-3 9100,280 r90 top locked (schematic designator J4)
J6 "Header_14_(7X2)_STR_SHD_col2" HDR_87831-1420 10130,1550 r180 top locked
L1 "8532-46LTR" 8532_inductor 550,1745 r270 top locked (schematic designator L2)
L2 "ZJYS51R5-M4PAT-01" ZJYS51R5-M4PA_INDCUTOR 790,2520 r0 top locked (schematic designator L3)
L3 "8532-46LTR" 8532_inductor 930,1745 r270 top locked (schematic designator L1)
L4 "50105C" 5000_inductor 5955,3000 r270 top locked (schematic designator L9)
L5 "8532-38LTR" 8532_inductor 5940,2280 r270 top locked (schematic designator L6)
L6 "8532-38LTR" 8532_inductor 9992.96,2751.92 r270 top locked (schematic designator L5)
L7 "50105C" 5000_inductor 10110,3590 r270 top locked (schematic designator L8)
L8 "50105C" 5000_INDUCTOR 10397.96,2631.92 r270 top locked (schematic designator L7)
L9 "8532-38LTR" 8532_inductor 10487.96,1851.92 r270 top locked (schematic designator L4)
Q1 "MMBT3906" SOT23 6770,2300 r270 top locked
Q2 "MMBT3906" SOT23 7070,2150 r0 top locked
Q3 "MMBT3904" SOT23 6500,2590 r180 bottom locked
R1 "0_jumper" 1206 420,2510 r270 top locked (schematic designator R2)
R2 "10000" 1206 520,700 r0 top locked (schematic designator R297)
R3 "0_jumper" 1206 720,560 r0 top locked (schematic designator R244)
R4 "0_jumper" 1206 730,370 r0 top locked (schematic designator R225)
R5 "20000" 1206 1060,890 r180 top locked (schematic designator R313)
R6 "10000" 1206 1270,770 r90 top locked (schematic designator R294)
R7 "10000" 1206 1330,480 r180 top locked (schematic designator R296)
R8 "0_jumper" 1206 1330,360 r180 top locked (schematic designator R245)
R9 "47500" 1206 1590,2500 r270 top locked (schematic designator R76)
R10 "47500" 1206 1420,2450 r0 top locked (schematic designator R77)
R11 "47500" 1206 1420,2180 r0 top locked (schematic designator R78)
R12 "47500" 1206 1450,1980 r0 top locked (schematic designator R79)
R13 "47500" 1206 1414.65,1803.11 r0 top locked (schematic designator R113)
R14 "47500" 1206 1414.65,1483.11 r0 top locked (schematic designator R114)
R15 "47500" 1206 1439.65,1208.11 r0 top locked (schematic designator R115)
R16 "47500" 1206 1444.65,893.11 r0 top locked (schematic designator R117)
R17 "4870" 1206 1730,2860 r180 top locked (schematic designator R20)
R18 "200000" 1206 1904.65,1583.11 r180 top locked (schematic designator R58)
R19 "301000" 1206 2004.65,2428.11 r0 top locked (schematic designator R64)
R20 "301000" 1206 2124.65,2303.11 r0 top locked (schematic designator R65)
R21 "301000" 1206 1954.65,2168.11 r270 top locked (schematic designator R66)
R22 "6810" 1206 1904.65,1463.11 r0 top locked (schematic designator R73)
R23 "4870" 1206 1894.65,1343.11 r180 top locked (schematic designator R53)
R24 "200000" 1206 1954.65,1153.11 r180 top locked (schematic designator R96)
R25 "56200" 1206 1900,650 r0 top locked (schematic designator R123)
R26 "10000" 1206 1964.65,1883.11 r270 top locked (schematic designator R62)
R27 "100000" 1206 2050,470 r90 top locked (schematic designator R303)
R28 "2000" 1206 2174.65,1493.11 r270 top locked (schematic designator R71)
R29 "0_jumper" 1206 2260,700 r0 top locked (schematic designator R88)
R30 "200000" 1206 2344.65,2308.11 r0 top locked (schematic designator R55)
R31 "33200" 1206 2344.65,1533.11 r0 top locked (schematic designator R86)
R32 "2000" 1206 2344.65,1173.11 r0 top locked (schematic designator R108)
R33 "200000" 1206 2474.65,3073.11 r90 top locked (schematic designator R408)
R34 "56200" 1206 2464.65,2868.11 r0 top locked (schematic designator R84)
R35 "20000" 1206 2639.65,3133.11 r0 top locked (schematic designator R410)
R36 "100" 1206 2644.65,2823.11 r90 top locked (schematic designator R74)
R37 "68100" 1206 2534.65,1663.11 r90 top locked (schematic designator R82)
R38 "4870" 1206 2594.65,2653.11 r0 top locked (schematic designator R52)
R39 "200000" 1206 2594.65,2523.11 r0 top locked (schematic designator R54)
R40 "2000" 1206 2594.65,2403.11 r0 top locked (schematic designator R70)
R41 "301000" 1206 2594.65,1963.11 r90 top locked (schematic designator R68)
R42 "6810" 1206 2644.65,993.11 r90 top locked (schematic designator R110)
R43 "100" 1206 2590,770 r0 top locked (schematic designator R112)
R44 "68100" 1206 2654.65,1693.11 r90 top locked (schematic designator R81)
R45 "40200" 1206 2890,370 r0 top locked (schematic designator R251)
R46 "4870" 1206 2880,2840 r0 top locked (schematic designator R21)
R47 "10000" 1206 2730,550 r90 top locked (schematic designator R370)
R48 "200000" 1206 3064.65,2463.11 r180 top locked (schematic designator R407)
R49 "0_jumper" 1206 3030,570 r0 top locked (schematic designator R380)
R50 "0_jumper" 1206 3170,720 r180 top locked (schematic designator R378)
R51 "10000" 1206 3110,380 r0 top locked (schematic designator R348)
R52 "301000" 1206 3300,1150 r270 top locked (schematic designator R103)
R53 "10000" 1206 3355,2475 r0 top locked (schematic designator R264)
R54 "0_jumper" 1206 3305,2285 r0 top locked (schematic designator R253)
R55 "0_jumper" 1206 3305,2165 r0 top locked (schematic designator R316)
R56 "10000" 1206 3305,1975 r0 top locked (schematic designator R321)
R57 "10000" 1206 3313.43,1395 r90 top locked (schematic designator R97)
R58 "10000" 1206 3475,1955 r90 top locked (schematic designator R323)
R59 "10000" 1206 3710,730 r0 top locked (schematic designator R351)
R60 "10000" 1206 3870,2460 r180 top locked (schematic designator R260)
R61 "10000" 1206 3745,1955 r90 top locked (schematic designator R327)
R62 "2000" 1206 3750,920 r180 top locked (schematic designator R107)
R63 "0_jumper" 1206 3760,580 r180 top locked (schematic designator R263)
R64 "10000" 1206 3710,380 r0 top locked (schematic designator R267)
R65 "1000" 1206 3815,3050 r270 top locked (schematic designator R246)
R66 "200000" 1206 3860,1560 r0 top locked (schematic designator R94)
R67 "0_jumper" 1206 3925,2285 r180 top locked (schematic designator R252)
R68 "0_jumper" 1206 3925,2165 r180 top locked (schematic designator R318)
R69 "10000" 1206 3925,1965 r180 top locked (schematic designator R324)
R70 "200000" 1206 3970,1000 r0 top locked (schematic designator R91)
R71 "6810" 1206 3960,780 r180 top locked (schematic designator R109)
R72 "40200" 1206 3930,380 r180 top locked (schematic designator R282)
R73 "1000" 1206 4015,3060 r270 top locked (schematic designator R226)
R74 "100000" 1206 4160,1610 r180 top locked (schematic designator R281)
R75 "200000" 1206 4010,1390 r270 top locked (schematic designator R93)
R76 "10000" 1206 3980,660 r180 top locked (schematic designator R354)
R77 "10000" 1206 4200,2550 r180 top locked (schematic designator R372)
R78 "1000" 1206 4135,3060 r270 top locked (schematic designator R248)
R79 "1210" 1206 4180,1490 r0 top locked (schematic designator R257)
R80 "100" 1206 4180,840 r0 top locked (schematic designator R111)
R81 "0_jumper" 1206 4160,500 r90 top locked (schematic designator R345)
R82 "2000" 1206 4470,3040 r90 top locked (schematic designator R231)
R83 "100000" 1206 4250,1300.12 r90 top locked (schematic designator R359)
R84 "1210" 1206 4250,1080.12 r90 top locked (schematic designator R365)
R85 "10000" 1206 4420,2550 r0 top locked (schematic designator R368)
R86 "100000" 1206 4430,2390 r180 top locked (schematic designator R330)
R87 "1210" 1206 4430,2275 r180 top locked (schematic designator R336)
R88 "10000" 1206 4440,2085 r180 top locked (schematic designator R266)
R89 "100000" 1206 4490,1835 r270 top locked (schematic designator R279)
R90 "10000" 1206 4400,1560 r180 top locked (schematic designator R369)
R91 "1210" 1206 4440,730 r90 top locked (schematic designator R311)
R92 "1210" 1206 4500,1000.12 r0 top locked (schematic designator R366)
R93 "2000" 1206 4660,3060 r90 top locked (schematic designator R194)
R94 "100000" 1206 4560,730 r270 top locked (schematic designator R305)
R95 "2000" 1206 4850,3070 r90 top locked (schematic designator R193)
R96 "100000" 1206 4800,1390 r180 top locked (schematic designator R275)
R97 "100000" 1206 5050,1930 r90 top locked (schematic designator R332)
R98 "100000" 1206 4930,1210 r270 top locked (schematic designator R306)
R99 "10000" 1206 4850,510 r270 top locked (schematic designator R298)
R100 "1210" 1206 4970,510 r90 top locked (schematic designator R312)
R101 "2000" 1206 5040,3070 r90 top locked (schematic designator R192)
R102 "1210" 1206 5010,1560 r270 top locked (schematic designator R255)
R103 "100000" 1206 5030,2360 r90 top locked (schematic designator R333)
R104 "1210" 1206 5070,2145 r270 top locked (schematic designator R338)
R105 "4870" 1206 5110,970 r270 top locked (schematic designator R293)
R106 "10000" 1206 5150,740 r270 top locked (schematic designator R249)
R107 "1210" 1206 5150,460 r90 top locked (schematic designator R284)
R108 "2000" 1206 5230,3070 r90 top locked (schematic designator R227)
R109 "100" 1206 5260,1530 r0 top locked (schematic designator R237)
R110 "4870" 1206 5290,960 r270 top locked (schematic designator R346)
R111 "2000" 1206 5320,2790 r90 top locked (schematic designator R198)
R112 "2000" 1206 5420,3040 r90 top locked (schematic designator R196)
R113 "10000" 1206 5400,2180 r0 top locked (schematic designator R216)
R114 "0_jumper" 1206 5410,960 r90 top locked (schematic designator R397)
R115 "100000" 1206 5420,370 r0 top locked (schematic designator R277)
R116 "2000" 1206 5510,2790 r90 top locked (schematic designator R197)
R117 "10000" 1206 5520,1510 r270 top locked (schematic designator R220)
R118 "2000" 1206 5570,3040 r90 top locked (schematic designator R195)
R119 "4870" 1206 5610,890 r270 top locked (schematic designator R319)
R120 "4870" 1206 5640.12,670.12 r270 top locked (schematic designator R258)
R121 "4870" 1206 5760,630 r270 top locked (schematic designator R347)
R122 "4870" 1206 5800,860 r270 top locked (schematic designator R375)
R123 "100" 1206 5830,1510 r270 top locked (schematic designator R239)
R124 "100" 1206 6070,1500 r180 top locked (schematic designator R206)
R125 "100" 1206 6090,1740 r180 top locked (schematic designator R234)
R126 "100" 1206 6090,1620 r180 top locked (schematic designator R236)
R127 "6810" 1206 6150,1160 r180 top locked (schematic designator R355)
R128 "10000" 1206 6260,2590 r0 top locked (schematic designator R171)
R129 "10000" 1206 6210,2340 r90 top locked (schematic designator R215)
R130 "10000" 1206 6300,530 r270 top locked (schematic designator R322)
R131 "100" 1206 6310,1690 r180 top locked (schematic designator R204)
R132 "10000" 1206 6250,1330 r90 top locked (schematic designator R349)
R133 "6810" 1206 6480,530 r270 top locked (schematic designator R328)
R134 "10000" 1206 6470,2320 r90 top locked (schematic designator R180)
R135 "10000" 1206 6540,1860 r0 top locked (schematic designator R217)
R136 "10000" 1206 6540,1620 r0 top locked (schematic designator R182)
R137 "6810" 1206 6440,1390 r270 top locked (schematic designator R301)
R138 "0_jumper" 1206 6835,725 r0 top locked (schematic designator R29)
R139 "0_jumper" 1206 6835,605 r0 top locked (schematic designator R27)
R140 "0_jumper" 1206 6835,485 r0 top locked (schematic designator R25)
R141 "0_jumper" 1206 6835,365 r0 top locked (schematic designator R23)
R142 "10000" 1206 6640,2320 r90 top locked (schematic designator R170)
R143 "10000" 1206 6640,1450 r270 top locked (schematic designator R295)
R144 "4870" 1206 6800,2500 r0 top locked (schematic designator R166)
R145 "249" 1206 6900,2330 r270 top locked (schematic designator R176)
R146 "10000" 1206 6850,2080 r90 top locked (schematic designator R173)
R147 "100" 1206 6940,1200 r270 top locked (schematic designator R211)
R148 "0_jumper" 1206 7135,995 r180 top locked (schematic designator R33)
R149 "0_jumper" 1206 7135,875 r180 top locked (schematic designator R30)
R150 "4870" 1206 7020,2020 r180 top locked (schematic designator R168)
R151 "0_jumper" 1206 7180,3075 r270 top locked (schematic designator R164)
R152 "249" 1206 7130,2340 r270 top locked (schematic designator R178)
R153 "0_jumper" 1206 7140,1350 r0 top locked (schematic designator R342)
R154 "0_jumper" 1206 7145,1230 r180 top locked (schematic designator R36)
R155 "0_jumper" 1206 7140,1115 r180 top locked (schematic designator R41)
R156 "10000" 1206 7410,1800 r180 top locked (schematic designator R186)
R157 "100" 1206 7320,2230 r180 top locked (schematic designator R174)
R158 "10000" 1206 7320,1990 r0 top locked (schematic designator R169)
R159 "0_jumper" 1206 7535,765 r0 top locked (schematic designator R28)
R160 "0_jumper" 1206 7630,385 r0 top locked (schematic designator R22)
R161 "0_jumper" 1206 7510,2630 r90 top locked (schematic designator R415)
R162 "4750" 1206 7660,2460 r180 top locked (schematic designator R126)
R163 "4750" 1206 7674.84,2340.04 r0 top locked (schematic designator R125)
R164 "100" 1206 7630,1800 r0 top locked (schematic designator R210)
R165 "205" 1206 7755,935 r180 top locked (schematic designator R49)
R166 "205" 1206 7755,815 r180 top locked (schematic designator R48)
R167 "205" 1206 7850,555 r180 top locked (schematic designator R43)
R168 "205" 1206 7850,435 r180 top locked (schematic designator R42)
R169 "100000" 1206 8100,2570 r180 top locked (schematic designator R127)
R170 "10000" 1206 8570,1460 r0 top locked (schematic designator R270)
R171 "10000" 1206 8577.96,1146.92 r180 top locked (schematic designator R149)
R172 "0_jumper" 1206 8577.96,1271.92 r0 top locked (schematic designator R133)
R173 "0_jumper" 1206 8697.96,1011.92 r180 top locked (schematic designator R129)
R174 "6810" 1206 8810,1540 r0 top locked (schematic designator R273)
R175 "10000" 1206 9017.96,1011.92 r0 top locked (schematic designator R148)
R176 "10000" 1206 9100,1490 r180 top locked (schematic designator R261)
R177 "0_jumper" 1206 9177.96,1271.92 r0 top locked (schematic designator R131)
R178 "0_jumper" 1206 9177.96,1141.92 r0 top locked (schematic designator R130)
R179 "0_jumper" 1206 9410,2080 r0 top locked (schematic designator R393)
R180 "0_jumper" 1206 9410,1900 r0 top locked (schematic designator R394)
R181 "10000" 1206 9420,1720 r0 top locked (schematic designator R374)
R182 "10000" 1206 9517.96,1136.92 r180 top locked (schematic designator R152)
R183 "0_jumper" 1206 9522.96,1251.92 r0 top locked (schematic designator R143)
R184 "0_jumper" 1206 9642.96,1011.92 r180 top locked (schematic designator R139)
R185 "10000" 1206 9962.96,1011.92 r0 top locked (schematic designator R151)
R186 "0_jumper" 1206 10117.96,1246.92 r0 top locked (schematic designator R141)
R187 "0_jumper" 1206 10122.96,1131.92 r0 top locked (schematic designator R140)
R188 "1210" 1206 510,860 r180 bottom locked (schematic designator R403)
R189 "0_jumper" 1206 510,740 r0 bottom locked (schematic designator R291)
R190 "15.8" 1206 630,1515 r270 bottom locked (schematic designator R16)
R191 "1210" 1206 770,850 r180 bottom locked (schematic designator R402)
R192 "0_jumper" 1206 730,370 r180 bottom locked (schematic designator R233)
R193 "1000" 1206 870,2345 r0 bottom locked (schematic designator R400)
R194 "0_jumper" 1206 960,2520 r270 bottom locked (schematic designator R1)
R195 "15.8" 1206 990,1525 r270 bottom locked (schematic designator R15)
R196 "10000" 1206 980,890 r270 bottom locked (schematic designator R300)
R197 "0_jumper" 1206 1355,3960 r0 bottom locked (schematic designator R5)
R198 "0_jumper" 1206 1275,3620 r0 bottom locked (schematic designator R7)
R199 "20000" 1206 1210,720 r270 bottom locked (schematic designator R250)
R200 "0_jumper" 1206 1360,480 r180 bottom locked (schematic designator R377)
R201 "0_jumper" 1206 1360,360 r180 bottom locked (schematic designator R376)
R202 "0_jumper" 1206 1460,4090 r180 bottom locked (schematic designator R11)
R203 "0_jumper" 1206 1495,3620 r180 bottom locked (schematic designator R10)
R204 "10000" 1206 1684.65,2463.11 r0 bottom locked (schematic designator R61)
R205 "10000" 1206 1674.65,1973.11 r180 bottom locked (schematic designator R63)
R206 "10000" 1206 1484.65,1753.11 r270 bottom locked (schematic designator R98)
R207 "10000" 1206 1440,760 r180 bottom locked (schematic designator R99)
R208 "0_jumper" 1206 1380,600 r180 bottom locked (schematic designator R289)
R209 "10000" 1206 1504.65,933.11 r270 bottom locked (schematic designator R100)
R210 "0_jumper" 1206 1580,3960 r180 bottom locked (schematic designator R12)
R211 "68100" 1206 1844.65,1883.11 r270 bottom locked (schematic designator R83)
R212 "68100" 1206 1674.65,673.11 r0 bottom locked (schematic designator R121)
R213 "0_jumper" 1206 1660,3560 r270 bottom locked (schematic designator R9)
R214 "200000" 1206 1944.65,1703.11 r0 bottom locked (schematic designator R59)
R215 "100" 1206 1894.65,1343.11 r0 bottom locked (schematic designator R75)
R216 "200000" 1206 1954.65,1153.11 r0 bottom locked (schematic designator R95)
R217 "100000" 1206 2295,375 r0 bottom locked (schematic designator R304)
R218 "68100" 1206 2070,2870 r0 bottom locked (schematic designator R80)
R219 "10000" 1206 2070,2690 r270 bottom locked (schematic designator R60)
R220 "301000" 1206 2180,1510 r90 bottom locked (schematic designator R104)
R221 "1210" 1206 2125,465 r270 bottom locked (schematic designator R309)
R222 "56200" 1206 2164.65,1883.11 r90 bottom locked (schematic designator R85)
R223 "301000" 1206 2204.65,1043.11 r270 bottom locked (schematic designator R105)
R224 "301000" 1206 2200,790 r90 bottom locked (schematic designator R106)
R225 "1210" 1206 2300,560 r0 bottom locked (schematic designator R310)
R226 "200000" 1206 2464.65,2763.11 r180 bottom locked (schematic designator R56)
R227 "100" 1206 2474.65,3073.11 r90 bottom locked (schematic designator R409)
R228 "0_jumper" 1206 2414.65,2113.11 r90 bottom locked (schematic designator R51)
R229 "6810" 1206 2594.65,2403.11 r0 bottom locked (schematic designator R72)
R230 "301000" 1206 2604.65,1793.11 r180 bottom locked (schematic designator R67)
R231 "20000" 1206 2639.65,3133.11 r180 bottom locked (schematic designator R411)
R232 "301000" 1206 2584.65,2213.11 r0 bottom locked (schematic designator R69)
R233 "33200" 1206 2594.65,1303.11 r0 bottom locked (schematic designator R124)
R234 "4870" 1206 2644.65,993.11 r270 bottom locked (schematic designator R90)
R235 "0_jumper" 1206 2824.65,2353.11 r0 bottom locked (schematic designator R50)
R236 "68100" 1206 2870,1570 r0 bottom locked (schematic designator R120)
R237 "0_jumper" 1206 2820,510 r270 bottom locked (schematic designator R343)
R238 "0_jumper" 1206 2980,790 r180 bottom locked (schematic designator R87)
R239 "10000" 1206 3010,370 r0 bottom locked (schematic designator R350)
R240 "68100" 1206 3090,1570 r0 bottom locked (schematic designator R119)
R241 "0_jumper" 1206 3170,660 r0 bottom locked (schematic designator R379)
R242 "301000" 1206 3335,1205 r180 bottom locked (schematic designator R102)
R243 "15000" 1206 3355,2475 r180 bottom locked (schematic designator R367)
R244 "15000" 1206 3305,1975 r180 bottom locked (schematic designator R314)
R245 "56200" 1206 3373.43,1565 r0 bottom locked (schematic designator R122)
R246 "68100" 1206 3313.43,1395 r270 bottom locked (schematic designator R118)
R247 "10000" 1206 3525,2415 r270 bottom locked (schematic designator R271)
R248 "10000" 1206 3705,2415 r270 bottom locked (schematic designator R262)
R249 "200000" 1206 3625,915 r0 bottom locked (schematic designator R92)
R250 "100" 1206 3770,2670 r180 bottom locked (schematic designator R241)
R251 "40200" 1206 3710,730 r180 bottom locked (schematic designator R283)
R252 "10000" 1206 3930,380 r180 bottom locked (schematic designator R269)
R253 "1000" 1206 3815,3050 r270 bottom locked (schematic designator R247)
R254 "15000" 1206 3875,2475 r0 bottom locked (schematic designator R341)
R255 "100" 1206 3850,1450 r0 bottom locked (schematic designator R412)
R256 "301000" 1206 3790,1210 r90 bottom locked (schematic designator R101)
R257 "15000" 1206 3925,1965 r0 bottom locked (schematic designator R340)
R258 "20000" 1206 3910,1140 r270 bottom locked (schematic designator R413)
R259 "4870" 1206 3940,750 r0 bottom locked (schematic designator R89)
R260 "1000" 1206 4015,3060 r270 bottom locked (schematic designator R232)
R261 "100" 1206 4020,2680 r180 bottom locked (schematic designator R235)
R262 "200000" 1206 4060,1320 r180 bottom locked (schematic designator R57)
R263 "20000" 1206 4100,1140 r90 bottom locked (schematic designator R414)
R264 "0_jumper" 1206 4170,380 r180 bottom locked (schematic designator R335)
R265 "100000" 1206 4470,1610 r0 bottom locked (schematic designator R278)
R266 "10000" 1206 4250,1080.12 r270 bottom locked (schematic designator R352)
R267 "100000" 1206 4430,2390 r180 bottom locked (schematic designator R331)
R268 "1210" 1206 4430,2275 r0 bottom locked (schematic designator R337)
R269 "1210" 1206 4490,1835 r90 bottom locked (schematic designator R256)
R270 "100000" 1206 4620,880 r180 bottom locked (schematic designator R357)
R271 "100000" 1206 4500,1070 r180 bottom locked (schematic designator R360)
R272 "2000" 1206 4660,3070 r90 bottom locked (schematic designator R191)
R273 "1210" 1206 4730,1000 r180 bottom locked (schematic designator R363)
R274 "2000" 1206 4850,3070 r90 bottom locked (schematic designator R228)
R275 "0_jumper" 1206 4860,370 r180 bottom locked (schematic designator R334)
R276 "10000" 1206 4900,2530 r0 bottom locked (schematic designator R371)
R277 "1210" 1206 4880,840 r180 bottom locked (schematic designator R364)
R278 "100000" 1206 4890,670 r270 bottom locked (schematic designator R358)
R279 "10000" 1206 4950,490 r0 bottom locked (schematic designator R116)
R280 "2000" 1206 5040,3070 r90 bottom locked (schematic designator R229)
R281 "1210" 1206 5010,1560 r90 bottom locked (schematic designator R254)
R282 "1210" 1206 5030,2360 r270 bottom locked (schematic designator R339)
R283 "10000" 1206 5070,2145 r270 bottom locked (schematic designator R325)
R284 "4870" 1206 5130,1100 r180 bottom locked (schematic designator R373)
R285 "0_jumper" 1206 5070,710 r270 bottom locked (schematic designator R317)
R286 "2000" 1206 5230,3070 r90 bottom locked (schematic designator R230)
R287 "10000" 1206 5260,1530 r0 bottom locked (schematic designator R218)
R288 "10000" 1206 5450,1340 r0 bottom locked (schematic designator R399)
R289 "100000" 1206 5220,910 r0 bottom locked (schematic designator R276)
R290 "2000" 1206 5320,2790 r90 bottom locked (schematic designator R199)
R291 "2000" 1206 5420,3040 r90 bottom locked (schematic designator R201)
R292 "0_jumper" 1206 5410,960 r90 bottom locked (schematic designator R398)
R293 "1210" 1206 5425,370 r180 bottom locked (schematic designator R285)
R294 "2000" 1206 5510,2800 r90 bottom locked (schematic designator R200)
R295 "10000" 1206 5520,1510 r270 bottom locked (schematic designator R222)
R296 "4870" 1206 5640,670 r270 bottom locked (schematic designator R320)
R297 "2000" 1206 5570,3040 r90 bottom locked (schematic designator R202)
R298 "10000" 1206 5640,2160 r90 bottom locked (schematic designator R224)
R299 "4870" 1206 5610,890 r270 bottom locked (schematic designator R259)
R300 "100" 1206 5770,1690 r180 bottom locked (schematic designator R243)
R301 "249" 1206 5730,2780 r270 bottom locked (schematic designator R406)
R302 "3.01" 1206 5850,1990 r270 bottom locked (schematic designator R19)
R303 "100" 1206 5890,1560 r0 bottom locked (schematic designator R208)
R304 "4870" 1206 5800,860 r270 bottom locked (schematic designator R265)
R305 "4870" 1206 5760,640 r270 bottom locked (schematic designator R292)
R306 "0_jumper" 1206 5885,2990 r270 bottom locked (schematic designator R14)
R307 "0_jumper" 1206 6005,2990 r270 bottom locked (schematic designator R13)
R308 "10000" 1206 6060,1740 r0 bottom locked (schematic designator R184)
R309 "6810" 1206 6190,1180 r180 bottom locked (schematic designator R356)
R310 "249" 1206 6190,2850 r180 bottom locked (schematic designator R177)
R311 "4870" 1206 6260,2590 r180 bottom locked (schematic designator R167)
R312 "10000" 1206 6250,1350 r90 bottom locked (schematic designator R353)
R313 "6810" 1206 6440,1070 r180 bottom locked (schematic designator R302)
R314 "100" 1206 6470,1870 r0 bottom locked (schematic designator R238)
R315 "100" 1206 6510,2400 r180 bottom locked (schematic designator R207)
R316 "10000" 1206 6560,1630 r0 bottom locked (schematic designator R219)
R317 "10000" 1206 6510,1460 r90 bottom locked (schematic designator R299)
R318 "0_jumper" 1206 6835,725 r180 bottom locked (schematic designator R40)
R319 "0_jumper" 1206 6835,605 r180 bottom locked (schematic designator R37)
R320 "0_jumper" 1206 6835,485 r180 bottom locked (schematic designator R34)
R321 "0_jumper" 1206 6835,365 r180 bottom locked (schematic designator R31)
R322 "10000" 1206 6680,2420 r270 bottom locked (schematic designator R183)
R323 "10000" 1206 6740,1730 r270 bottom locked (schematic designator R181)
R324 "10000" 1206 6710,1420 r90 bottom locked (schematic designator R268)
R325 "6810" 1206 6720,980 r270 bottom locked (schematic designator R274)
R326 "100" 1206 6920,2030 r180 bottom locked (schematic designator R205)
R327 "0_jumper" 1206 6890,3025 r270 bottom locked (schematic designator R162)
R328 "10000" 1206 6900,1490 r90 bottom locked (schematic designator R187)
R329 "0_jumper" 1206 7145,1230 r180 bottom locked (schematic designator R38)
R330 "0_jumper" 1206 7140,1115 r180 bottom locked (schematic designator R39)
R331 "0_jumper" 1206 7135,995 r180 bottom locked (schematic designator R35)
R332 "0_jumper" 1206 7135,875 r180 bottom locked (schematic designator R32)
R333 "0_jumper" 1206 7030,2820 r0 bottom locked (schematic designator R163)
R334 "249" 1206 7070,1620 r90 bottom locked (schematic designator R161)
R335 "0_jumper" 1206 7180,3070 r90 bottom locked (schematic designator R165)
R336 "249" 1206 7250,1600 r90 bottom locked (schematic designator R160)
R337 "10000" 1206 7450,3190 r180 bottom locked (schematic designator R190)
R338 "100" 1206 7450,3070 r180 bottom locked (schematic designator R214)
R339 "100" 1206 7320,2230 r180 bottom locked (schematic designator R175)
R340 "10000" 1206 7320,1990 r0 bottom locked (schematic designator R172)
R341 "10000" 1206 7370,1850 r180 bottom locked (schematic designator R185)
R342 "100" 1206 7500,1730 r0 bottom locked (schematic designator R209)
R343 "0_jumper" 1206 7530,765 r0 bottom locked (schematic designator R26)
R344 "0_jumper" 1206 7630,385 r0 bottom locked (schematic designator R24)
R345 "10000" 1206 7620,2590 r90 bottom locked (schematic designator R189)
R346 "100" 1206 7620,2370 r270 bottom locked (schematic designator R213)
R347 "100" 1206 7710,1970 r90 bottom locked (schematic designator R203)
